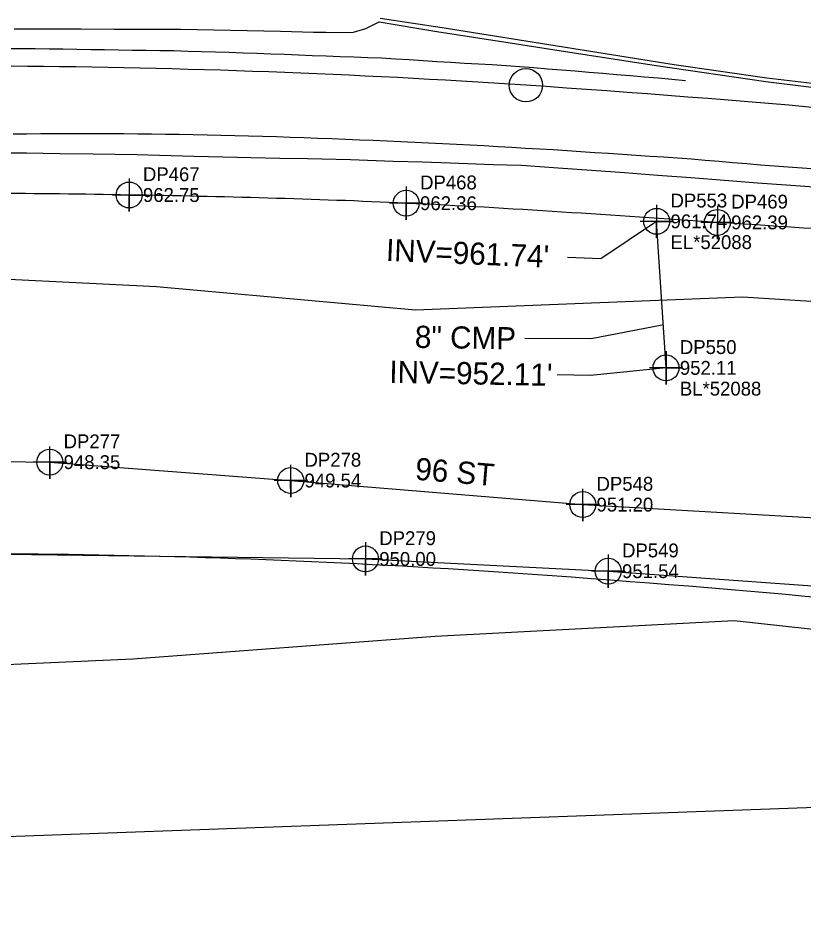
# Model space of a CAD drawing. Extents: x 1182322 to 1186765, y 572295 to 575411.
# Drawn here: x 1185141.8 to 1185283.6, y 573657.5 to 573821.6 of the extents above; entities that cross this region are included whole.
import ezdxf

# ---------------------------------------------------------------- set-up
doc = ezdxf.new("R2010")
doc.units = 0
for name, color, linetype in [('COGO Default Chain', 7, 'Continuous'), ('Exist Guardrail', 7, 'Continuous'), ('Exist Guardrail Cogo Elevation', 7, 'Continuous'), ('Exist Guardrail Cogo Number', 7, 'Continuous'), ('Exist Guardrail Cogo Point CELL', 7, 'Continuous'), ('Exist Horizontal Alignment', 7, 'Continuous'), ('Exist Horizontal Alignment Point', 7, 'Continuous'), ('Exist Other Culture Fence Line', 7, 'Continuous'), ('Exist Other Culture Fence Line Cogo Elevation', 7, 'Continuous'), ('Exist Other Culture Fence Line Cogo Number', 7, 'Continuous'), ('Exist Other Culture Fence Line Cogo Point CELL', 7, 'Continuous'), ('Exist Right of Way Line', 7, 'Continuous'), ('Exist Roads Curbs', 7, 'Continuous'), ('Exist Roads EOP', 7, 'Continuous'), ('Exist Roads EOT', 7, 'Continuous'), ('Exist Structure Minor Pipes CMP 8 Inch', 7, 'Continuous'), ('Exist Structure Minor Pipes CMP 8 Inch Cogo Comment', 7, 'Continuous'), ('Exist Structure Minor Pipes CMP 8 Inch Cogo Elevation', 7, 'Continuous'), ('Exist Structure Minor Pipes CMP 8 Inch Cogo Number', 7, 'Continuous'), ('Exist Structure Minor Pipes CMP 8 Inch Cogo Point CELL', 7, 'Continuous'), ('Exist Structure Minor Pipes CMP 8 Inch Invert', 7, 'Continuous'), ('Exist Structure Minor Pipes CMP 8 Inch Leader', 7, 'Continuous'), ('Exist Structure Minor Pipes CMP 8 Inch Text', 7, 'Continuous'), ('Exist Utilities Telephone UG Conduit SUE LOS B', 7, 'Continuous'), ('Exist Utilities Telephone UG Conduit SUE LOS B Cogo Elevation', 7, 'Continuous'), ('Exist Utilities Telephone UG Conduit SUE LOS B Cogo Number', 7, 'Continuous'), ('Exist Utilities Telephone UG Conduit SUE LOS B Cogo Point CELL', 7, 'Continuous'), ('Exist Utilities Telephone UG Conduit SUE LOS B Text', 7, 'Continuous'), ('Exist Vegetation Woods Line', 7, 'Continuous'), ('Sheet Layout Plan Border', 7, 'Continuous')]:
    doc.layers.add(name, color=color, linetype=linetype)

msp = doc.modelspace()

# ---------------------------------------------------------------- linework, layer by layer
at = {"layer": 'COGO Default Chain'}
for centre, radius, start, end in [((1185128.8, 572235.35), 1577.62, 86.1973, 92.94509), ((1185071.3, 571370.22), 2444.65, 83.45501, 86.1973)]:
    msp.add_arc(centre, radius, start, end, dxfattribs=at)
at = {"layer": 'Exist Guardrail'}
msp.add_spline([(1185594.93, 573734.55), (1185552.15, 573743.92), (1185503.35, 573753.48), (1185460.44, 573761.12), (1185417.11, 573768.48), (1185367.38, 573775.86), (1185317.73, 573781.22), (1185267.96, 573784.75), (1185211.84, 573788.21), (1185161.85, 573789.69), (1185111.95, 573789.89), (1185061.93, 573788.34)], degree=3, dxfattribs=at)
at = {"layer": 'Exist Guardrail Cogo Point CELL'}
for points in [[(1185161.85, 573792.69), (1185161.85, 573786.69), (1185161.85, 573789.69), (1185164.85, 573789.69), (1185158.85, 573789.69)], [(1185211.84, 573791.21), (1185211.84, 573785.21), (1185211.84, 573788.21), (1185214.84, 573788.21), (1185208.84, 573788.21)], [(1185267.96, 573787.75), (1185267.96, 573781.75), (1185267.96, 573784.75), (1185270.96, 573784.75), (1185264.96, 573784.75)]]:
    msp.add_lwpolyline(points, dxfattribs=at)
for centre in [(1185161.85, 573789.69), (1185211.84, 573788.21), (1185267.96, 573784.75)]:
    msp.add_circle(centre, 2.34, dxfattribs=at)
at = {"layer": 'Exist Horizontal Alignment'}
for centre, radius, start, end in [((1185128.8, 572235.35), 1577.62, 86.1973, 92.94509), ((1185071.3, 571370.22), 2444.65, 83.45501, 86.1973)]:
    msp.add_arc(centre, radius, start, end, dxfattribs=at)
at = {"layer": 'Exist Horizontal Alignment Point'}
msp.add_circle((1185233.43, 573809.49), 3, dxfattribs=at)
at = {"layer": 'Exist Other Culture Fence Line'}
msp.add_lwpolyline([(1184699.34, 573697.51), (1184773.78, 573703.02), (1184848.65, 573709.06), (1184900.84, 573713.11), (1184965.64, 573718.36), (1185023.1, 573721.56), (1185061.74, 573723.1), (1185125.69, 573725.08), (1185204.48, 573724.02), (1185248.27, 573721.81), (1185300.17, 573718.11), (1185350.66, 573712.74), (1185422.95, 573702.8), (1185464.84, 573695.68), (1185533.29, 573681.7), (1185567.96, 573674.22), (1185634.32, 573659.17)], dxfattribs=at)
at = {"layer": 'Exist Other Culture Fence Line Cogo Point CELL'}
for points in [[(1185204.48, 573727.02), (1185204.48, 573721.02), (1185204.48, 573724.02), (1185207.48, 573724.02), (1185201.48, 573724.02)], [(1185248.27, 573724.81), (1185248.27, 573718.81), (1185248.27, 573721.81), (1185251.27, 573721.81), (1185245.27, 573721.81)]]:
    msp.add_lwpolyline(points, dxfattribs=at)
for centre in [(1185204.48, 573724.02), (1185248.27, 573721.81)]:
    msp.add_circle(centre, 2.34, dxfattribs=at)
at = {"layer": 'Exist Right of Way Line'}
for centre, radius, start, end in [((1185128.8, 572235.35), 1489.62, 86.1973, 92.94509), ((1185071.3, 571370.22), 2356.65, 83.45501, 86.1973)]:
    msp.add_arc(centre, radius, start, end, dxfattribs=at)
at = {"layer": 'Exist Roads Curbs'}
msp.add_lwpolyline([(1185207.12, 573821.6), (1185218.35, 573819.89), (1185237.58, 573816.83), (1185260.15, 573813.27), (1185276.9, 573810.85), (1185285.05, 573809.87), (1185303.43, 573808.41), (1185325.26, 573806.58), (1185353.56, 573803.47), (1185384.69, 573799.63), (1185391.99, 573798.48), (1185392.8, 573798.56), (1185392.86, 573798.99), (1185392.62, 573799.19), (1185385.29, 573800.81)], dxfattribs=at)
at = {"layer": 'Exist Roads EOP'}
for points in [[(1185141.13, 573819.65), (1185147.13, 573819.65), (1185153.13, 573819.65), (1185159.13, 573819.64), (1185165.13, 573819.63), (1185171.13, 573819.61), (1185177.13, 573819.49), (1185183.13, 573819.36), (1185189.13, 573819.23), (1185195.13, 573819.1), (1185197.28, 573819.06)], [(1185197.34, 573819.06), (1185199.84, 573819.03), (1185202.34, 573819.07), (1185204.53, 573819.72), (1185206.95, 573820.91)], [(1185206.95, 573820.92), (1185217.38, 573819.2), (1185230.6, 573817.16), (1185238.63, 573815.86), (1185256.94, 573813.04), (1185276.69, 573810.19), (1185284.95, 573809.14), (1185303.22, 573807.67), (1185325.21, 573805.89), (1185353.47, 573802.71), (1185384.64, 573799.05), (1185391.94, 573798.06), (1185393.01, 573798.15), (1185393.25, 573798.51), (1185393.25, 573798.99), (1185393, 573799.4), (1185390.67, 573799.99), (1185385.26, 573801.21)], [(1185287.11, 573790.96), (1185281.19, 573791.4), (1185275.21, 573791.85), (1185269.22, 573792.31), (1185263.18, 573792.77), (1185257.22, 573793.23), (1185251.21, 573793.68), (1185245.23, 573794.1), (1185239.26, 573794.51), (1185232.66, 573794.99), (1185227.5, 573795.13), (1185219.78, 573795.43), (1185214.71, 573795.59), (1185209.49, 573795.75), (1185201.78, 573796.02), (1185194.02, 573796.19), (1185189.01, 573796.29), (1185183.81, 573796.39), (1185178.73, 573796.5), (1185173.61, 573796.64), (1185167.33, 573796.84), (1185163.28, 573796.95), (1185155.35, 573797.07), (1185149.35, 573797.15), (1185143.35, 573797.22), (1185137.35, 573797.22)]]:
    msp.add_lwpolyline(points, dxfattribs=at)
at = {"layer": 'Exist Roads EOT'}
for points in [[(1185262.24, 573810.31), (1185259.75, 573810.54), (1185257.26, 573810.77), (1185254.77, 573810.97), (1185252.28, 573811.18), (1185249.79, 573811.39), (1185247.29, 573811.6), (1185244.8, 573811.8), (1185242.31, 573812.01), (1185239.82, 573812.22), (1185237.33, 573812.42), (1185234.84, 573812.61), (1185232.34, 573812.8), (1185229.85, 573812.99), (1185227.36, 573813.17), (1185224.86, 573813.31), (1185222.37, 573813.45), (1185219.87, 573813.6), (1185217.37, 573813.74), (1185214.88, 573813.9), (1185212.38, 573814.06), (1185209.89, 573814.22), (1185207.39, 573814.36), (1185204.89, 573814.45), (1185202.4, 573814.54), (1185199.9, 573814.64), (1185197.4, 573814.73), (1185194.9, 573814.83), (1185192.4, 573814.94), (1185189.91, 573815.04), (1185187.41, 573815.13), (1185184.91, 573815.22), (1185182.41, 573815.31), (1185179.91, 573815.4), (1185177.41, 573815.48), (1185174.92, 573815.55), (1185172.42, 573815.61), (1185169.92, 573815.68), (1185167.42, 573815.73), (1185164.92, 573815.76), (1185162.42, 573815.79), (1185159.92, 573815.83), (1185157.42, 573815.86), (1185154.92, 573815.91), (1185152.42, 573815.95), (1185149.92, 573815.99), (1185147.42, 573816.03), (1185144.92, 573816.04), (1185142.42, 573816.05), (1185139.92, 573816.06)], [(1185285.72, 573794.35), (1185283.23, 573794.54), (1185280.74, 573794.72), (1185278.24, 573794.91), (1185275.75, 573795.1), (1185273.26, 573795.3), (1185270.77, 573795.5), (1185268.28, 573795.71), (1185265.79, 573795.93), (1185263.29, 573796.14), (1185260.8, 573796.32), (1185258.31, 573796.5), (1185255.81, 573796.66), (1185253.32, 573796.82), (1185250.82, 573796.99), (1185248.33, 573797.16), (1185245.83, 573797.33), (1185243.34, 573797.5), (1185240.85, 573797.68), (1185238.35, 573797.83), (1185235.86, 573797.96), (1185233.36, 573798.1), (1185230.86, 573798.25), (1185228.37, 573798.4), (1185225.87, 573798.55), (1185223.38, 573798.69), (1185220.88, 573798.82), (1185218.38, 573798.93), (1185215.88, 573799.04), (1185213.39, 573799.17), (1185210.89, 573799.3), (1185208.39, 573799.4), (1185205.9, 573799.5), (1185203.4, 573799.6), (1185200.9, 573799.71), (1185198.4, 573799.82), (1185195.9, 573799.91), (1185193.41, 573800), (1185190.91, 573800.08), (1185188.41, 573800.17), (1185185.91, 573800.27), (1185183.41, 573800.32), (1185180.91, 573800.37), (1185178.41, 573800.42), (1185175.91, 573800.48), (1185173.41, 573800.53), (1185170.91, 573800.58), (1185168.41, 573800.63), (1185165.92, 573800.66), (1185163.42, 573800.69), (1185160.92, 573800.71), (1185158.42, 573800.74), (1185155.92, 573800.76), (1185153.42, 573800.75), (1185150.92, 573800.74), (1185148.42, 573800.72), (1185145.92, 573800.71), (1185143.42, 573800.7), (1185140.92, 573800.7)]]:
    msp.add_lwpolyline(points, dxfattribs=at)
at = {"layer": 'Exist Structure Minor Pipes CMP 8 Inch'}
msp.add_line((1185258.7, 573758.5), (1185257.01, 573784.94), dxfattribs=at)
at = {"layer": 'Exist Structure Minor Pipes CMP 8 Inch Cogo Point CELL'}
for points in [[(1185257.01, 573787.94), (1185257.01, 573781.94), (1185257.01, 573784.94), (1185260.01, 573784.94), (1185254.01, 573784.94)], [(1185258.7, 573761.5), (1185258.7, 573755.5), (1185258.7, 573758.5), (1185261.7, 573758.5), (1185255.7, 573758.5)]]:
    msp.add_lwpolyline(points, dxfattribs=at)
for centre in [(1185257.01, 573784.94), (1185258.7, 573758.5)]:
    msp.add_circle(centre, 2.34, dxfattribs=at)
at = {"layer": 'Exist Structure Minor Pipes CMP 8 Inch Leader'}
for points in [[(1185257.01, 573784.94), (1185246.92, 573778.19), (1185240.93, 573778.44)], [(1185258.01, 573766.21), (1185245.2, 573763.76), (1185233.26, 573763.82)], [(1185258.7, 573758.5), (1185245.08, 573757.11), (1185239.08, 573757.22)]]:
    msp.add_lwpolyline(points, dxfattribs=at)
at = {"layer": 'Exist Utilities Telephone UG Conduit SUE LOS B'}
msp.add_lwpolyline([(1184705.2, 573717.51), (1184761.61, 573719.92), (1184808.75, 573719.14), (1184855.63, 573717.48), (1184899.38, 573717.73), (1184947.65, 573726.76), (1184989.59, 573731.99), (1185049.6, 573740.86), (1185104.23, 573742.11), (1185147.54, 573741.49), (1185190.99, 573738.17), (1185243.67, 573733.83), (1185296.19, 573730.81), (1185343.76, 573727.54), (1185391.61, 573722.1), (1185423.08, 573716.53), (1185467.66, 573711.88), (1185536.39, 573704.97), (1185583.2, 573696.39), (1185626.44, 573682.88)], dxfattribs=at)
at = {"layer": 'Exist Utilities Telephone UG Conduit SUE LOS B Cogo Point CELL'}
for points in [[(1185147.52, 573744.3), (1185147.55, 573738.49), (1185147.54, 573741.49), (1185150.55, 573741.49), (1185144.55, 573741.49)], [(1185190.97, 573740.98), (1185191, 573735.17), (1185190.99, 573738.17), (1185194, 573738.17), (1185188, 573738.17)], [(1185243.65, 573736.65), (1185243.68, 573730.83), (1185243.67, 573733.83), (1185246.68, 573733.83), (1185240.68, 573733.83)]]:
    msp.add_lwpolyline(points, dxfattribs=at)
for centre in [(1185147.55, 573741.49), (1185191, 573738.17), (1185243.68, 573733.83)]:
    msp.add_circle(centre, 2.34, dxfattribs=at)
at = {"layer": 'Exist Vegetation Woods Line'}
for points in [[(1184575.02, 573729.05), (1184597.15, 573732.62), (1184637.97, 573736.65), (1184706.19, 573743.8), (1184765.1, 573753.09), (1184813.5, 573755.42), (1184873.05, 573752.61), (1184920.1, 573754.56), (1184952.91, 573761.14), (1185024.52, 573770.05), (1185065.05, 573766.23), (1185104.79, 573771.63), (1185125.52, 573775.21), (1185166.8, 573773.18), (1185213.51, 573768.99), (1185272.49, 573771.32), (1185349.48, 573766.46), (1185397.23, 573756.66)], [(1185359.01, 573702.12), (1185320.37, 573707.45), (1185270.98, 573712.83), (1185217.04, 573710.02), (1185162.54, 573705.94), (1185115.44, 573703.83), (1185057.71, 573705.66), (1185038.72, 573704.43), (1185023.43, 573695.62), (1185025.14, 573676.09), (1185031.21, 573657.46)]]:
    msp.add_lwpolyline(points, dxfattribs=at)
at = {"layer": 'Sheet Layout Plan Border'}
msp.add_line((1184830.48, 573662.79), (1185374.39, 573682.41), dxfattribs=at)

# ---------------------------------------------------------------- texts
at = {"layer": 'Exist Guardrail Cogo Elevation'}
for s, p in [('962.75', (1185164.35, 573788.44)), ('962.36', (1185214.34, 573786.96)), ('962.39', (1185270.46, 573783.5))]:
    msp.add_text(s, height=2.5, dxfattribs=at).set_placement(p)
at = {"layer": 'Exist Guardrail Cogo Number'}
for s, p in [('DP467', (1185164.35, 573792.19)), ('DP468', (1185214.34, 573790.71)), ('DP469', (1185270.46, 573787.25))]:
    msp.add_text(s, height=2.5, dxfattribs=at).set_placement(p)
at = {"layer": 'Exist Other Culture Fence Line Cogo Elevation'}
for s, p in [('950.00', (1185206.98, 573722.77)), ('951.54', (1185250.77, 573720.56))]:
    msp.add_text(s, height=2.5, dxfattribs=at).set_placement(p)
at = {"layer": 'Exist Other Culture Fence Line Cogo Number'}
for s, p in [('DP279', (1185206.98, 573726.52)), ('DP549', (1185250.77, 573724.31))]:
    msp.add_text(s, height=2.5, dxfattribs=at).set_placement(p)
at = {"layer": 'Exist Structure Minor Pipes CMP 8 Inch Cogo Comment'}
for s, p in [('EL*52088', (1185259.51, 573779.94)), ('BL*52088', (1185261.2, 573753.5))]:
    msp.add_text(s, height=2.5, dxfattribs=at).set_placement(p)
at = {"layer": 'Exist Structure Minor Pipes CMP 8 Inch Cogo Elevation'}
for s, p in [('961.74', (1185259.51, 573783.69)), ('952.11', (1185261.2, 573757.25))]:
    msp.add_text(s, height=2.5, dxfattribs=at).set_placement(p)
at = {"layer": 'Exist Structure Minor Pipes CMP 8 Inch Cogo Number'}
for s, p in [('DP553', (1185259.51, 573787.44)), ('DP550', (1185261.2, 573761))]:
    msp.add_text(s, height=2.5, dxfattribs=at).set_placement(p)
at = {"layer": 'Exist Structure Minor Pipes CMP 8 Inch Invert'}
for s, rotation, p in [("INV=961.74'", 357.6312, (1185208.13, 573777.8)), ("INV=952.11'", 358.8854, (1185208.76, 573755.81))]:
    msp.add_text(s, height=4, rotation=rotation, dxfattribs=at).set_placement(p)
at = {"layer": 'Exist Structure Minor Pipes CMP 8 Inch Text'}
msp.add_text('8" CMP', height=4, rotation=359.0646, dxfattribs=at).set_placement((1185213.37, 573762.12))
at = {"layer": 'Exist Utilities Telephone UG Conduit SUE LOS B Cogo Elevation'}
for s, p in [('948.35', (1185150.04, 573740.24)), ('949.54', (1185193.49, 573736.92)), ('951.20', (1185246.17, 573732.58))]:
    msp.add_text(s, height=2.5, dxfattribs=at).set_placement(p)
at = {"layer": 'Exist Utilities Telephone UG Conduit SUE LOS B Cogo Number'}
for s, p in [('DP277', (1185150.04, 573743.99)), ('DP278', (1185193.49, 573740.67)), ('DP548', (1185246.17, 573736.33))]:
    msp.add_text(s, height=2.5, dxfattribs=at).set_placement(p)
at = {"layer": 'Exist Utilities Telephone UG Conduit SUE LOS B Text'}
msp.add_text('96 ST', height=4, rotation=355.2995, dxfattribs=at).set_placement((1185213.35, 573738.33))

doc.saveas('drawing.dxf')
